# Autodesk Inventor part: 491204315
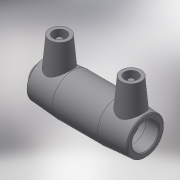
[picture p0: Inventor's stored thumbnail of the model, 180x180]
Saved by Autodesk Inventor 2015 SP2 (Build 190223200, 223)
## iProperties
Created: 2017-06
Part Number: 491204315
Material: Generic
Description: PLASSON END CAP 315
Document SubType Name: Modeling
Designer: KIM
Mass: 38.9236 g
Surface Area: 152.394 cm^2
Volume: 38.9236 cm^3
Density: 1 g/cm^3
Appearance: Default
Author: KIM
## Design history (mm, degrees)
derived "491204.ipt"
feature "Solid1::491204.ipt"
tag "TaggingFeature1"
body "Solid1"
other parameters: "d0" = 282, "d1" = 315, "d2" = 387, "d3" = 139, "d4" = 101.25, "d5" = 348.3, "d6" = 299.25, "d7" = 315, "d8" = 168 deg, "d10" = 55.6, "d11" = 18.53333, "d13" = 324, "d14" = 17.6296, "d15" = 139, "d16" = 139, "d17" = 299.25, "d18" = 315, "d19" = 3.52592, "d20" = 168 deg, "d22" = 363.78, "d23" = 387, "d24" = 352.8666, "d25" = 135 deg, "d26" = 145.8, "d27" = 135 deg, "d29" = 184, "d30" = 15, "d31" = 129.6, "d34" = 5 deg, "d35" = 15, "d39" = 5 deg, "d41" = 4, "d42" = 14, "d43" = 0, "d45" = 4, "d46" = 14, "d47" = 0, "d48" = 405, "d49" = 1, "d51" = 252, "d52" = 7.29, "d53" = 346.5, "d54" = 7.29, "d56" = 31.5, "d57" = 9.45, "d60" = 60.75, "d61" = 6.3, "d63" = 405, "d64" = 1, "d66" = 252, "d67" = 63, "d68" = 346.5, "d69" = 8.1, "d70" = 0, "d71" = 7.29, "d72" = 3, "d73" = 0, "d74" = 40.31, "d75" = 13.43667, "d76" = 3, "d77" = 0, "d_" = 315, "L_" = 405, "L_1" = 139, "D_" = 387, "A_" = 184, "d_2" = 12, "L_0" = 282, "d55" = 31.5
